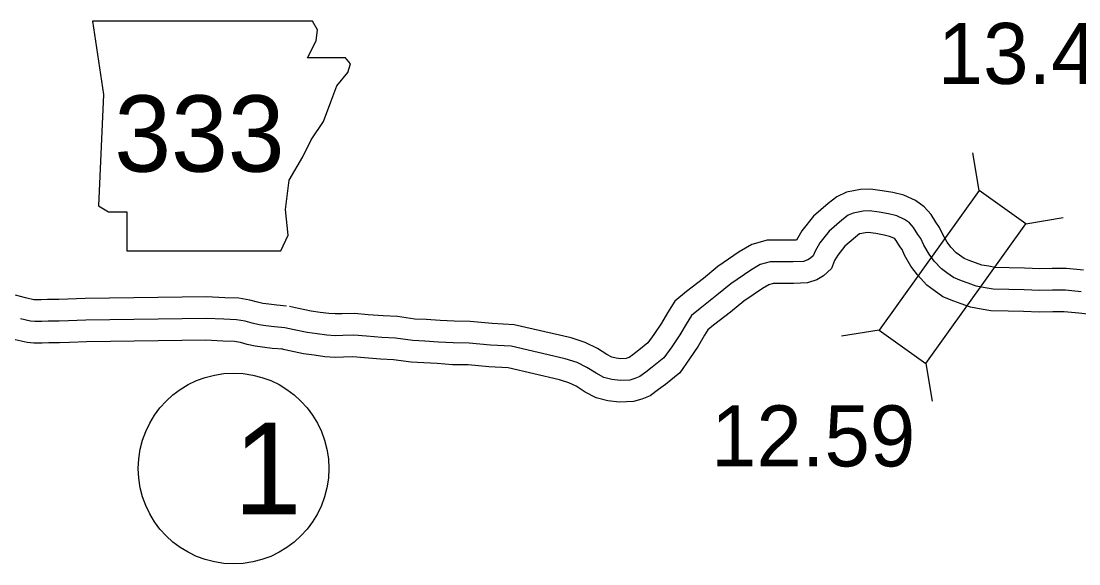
# Model space of a CAD drawing. Extents: x -83719 to 153526, y -11835 to 11446.
# Drawn here: x -2257.4 to -2013.5, y 1927.3 to 2052.4 of the extents above; entities that cross this region are included whole.
import ezdxf

# ---------------------------------------------------------------- set-up
doc = ezdxf.new("R2010")
doc.units = 0
for name, color, linetype in [('Level 11', 7, 'Continuous'), ('Level 20', 7, 'Continuous'), ('Level 21', 7, 'Continuous'), ('Level 25', 7, 'Continuous'), ('Level 27', 7, 'Continuous'), ('Level 58', 7, 'Continuous'), ('Level 59', 7, 'Continuous')]:
    doc.layers.add(name, color=color, linetype=linetype)

msp = doc.modelspace()

# ---------------------------------------------------------------- linework, layer by layer
at = {"layer": 'Level 11'}
for points in [[(-2012.39, 1995), (-2016.34, 1995.43), (-2019.58, 1995.38), (-2022.43, 1995.34), (-2025.96, 1995.49), (-2029.54, 1995.55), (-2032.74, 1995.63), (-2034.24, 1995.9), (-2035.87, 1996.18), (-2037.31, 1996.71), (-2038.78, 1997.21), (-2039.93, 1997.69), (-2040.99, 1998.44), (-2041.79, 1999.03), (-2042.96, 2000.31), (-2043.83, 2001.47), (-2044.75, 2003.09), (-2045.57, 2004.84), (-2046.45, 2006.05), (-2047.54, 2007.82), (-2049.16, 2009.65), (-2051.12, 2011.07), (-2053.83, 2012.3), (-2056.34, 2012.92), (-2058.82, 2013.33), (-2061.52, 2013.68), (-2063.79, 2013.62), (-2067.06, 2012.99), (-2069.3, 2011.95), (-2071.32, 2010.38), (-2074.65, 2007.48), (-2077.36, 2004.12), (-2078.6, 2001.96), (-2079.44, 2001.92), (-2082.09, 2001.95), (-2085.33, 2001.9), (-2088.89, 2000.96), (-2091.78, 1999.25), (-2096.77, 1995.87), (-2100.08, 1993.12), (-2103.97, 1990.1), (-2106.65, 1987.89), (-2108.35, 1985.16), (-2109.72, 1982.8), (-2111.5, 1980.19), (-2112.88, 1978.21), (-2114.93, 1976.55), (-2116.35, 1975.5), (-2117.2, 1974.87), (-2117.5, 1974.75), (-2117.89, 1974.64), (-2119.08, 1974.58), (-2120.21, 1974.72), (-2121.22, 1974.98), (-2122.33, 1975.56), (-2124.51, 1976.95), (-2127.31, 1978.32), (-2130.6, 1979.4), (-2143.69, 1982.41), (-2148.83, 1982.72), (-2153.86, 1983.19), (-2157.59, 1983.21), (-2160.8, 1983.42), (-2164.05, 1983.65), (-2166.65, 1983.74), (-2170.61, 1984.29), (-2173.91, 1984.45), (-2177.39, 1984.74), (-2180.56, 1985.02), (-2183.38, 1984.97), (-2184.99, 1984.91), (-2186.45, 1984.98), (-2188.45, 1985.27), (-2190.58, 1985.58), (-2193.44, 1986.17), (-2195.55, 1986.63)], [(-2008.19, 1984.46), (-2013.49, 1985.06), (-2016.81, 1985.42), (-2019.43, 1985.38), (-2022.58, 1985.34), (-2026.25, 1985.5), (-2029.74, 1985.55), (-2033.74, 1985.65), (-2035.97, 1986.05), (-2038.48, 1986.48), (-2040.64, 1987.28), (-2042.3, 1987.84), (-2044.82, 1988.89), (-2046.84, 1990.33), (-2048.5, 1991.54), (-2050.67, 1993.93), (-2052.21, 1995.97), (-2053.64, 1998.49), (-2054.22, 1999.74), (-2054.76, 2000.47), (-2055.6, 2001.84), (-2055.93, 2002.2), (-2056.17, 2002.38), (-2057.12, 2002.81), (-2058.35, 2003.12), (-2060.28, 2003.43), (-2062.04, 2003.67), (-2062.7, 2003.65), (-2063.96, 2003.4), (-2064.06, 2003.36), (-2064.96, 2002.65), (-2067.42, 2000.52), (-2069.08, 1998.45), (-2069.79, 1997.23), (-2070.48, 1995.43), (-2072.35, 1993.74), (-2073.89, 1992.81), (-2076.08, 1992.07), (-2079.25, 1991.92), (-2082.06, 1991.95), (-2083.95, 1991.92), (-2084.99, 1991.64), (-2086.43, 1990.8), (-2090.75, 1987.86), (-2093.82, 1985.32), (-2097.72, 1982.29), (-2099.02, 1981.22), (-2099.78, 1980), (-2101.26, 1977.46), (-2103.26, 1974.52), (-2105.48, 1971.34), (-2108.81, 1968.64), (-2110.39, 1967.47), (-2112.32, 1966.03), (-2114.29, 1965.27), (-2116.23, 1964.71), (-2119.44, 1964.55), (-2122.1, 1964.87), (-2124.84, 1965.6), (-2127.33, 1966.88), (-2129.42, 1968.22), (-2131.09, 1969.04), (-2133.28, 1969.75), (-2145.12, 1972.48), (-2149.59, 1972.75), (-2154.36, 1973.19), (-2157.96, 1973.21), (-2161.48, 1973.45), (-2164.57, 1973.66), (-2167.5, 1973.76), (-2171.54, 1974.32), (-2174.57, 1974.47), (-2178.23, 1974.77), (-2180.92, 1975.01), (-2183.1, 1974.97), (-2185.03, 1974.9), (-2187.43, 1975.01), (-2189.89, 1975.38), (-2192.3, 1975.72), (-2195.51, 1976.38), (-2197.67, 1976.85)], [(-2196.21, 1986.72), (-2198.49, 1986.91), (-2200.35, 1987.14), (-2201.66, 1987.35), (-2202.96, 1987.61), (-2204.68, 1988.1), (-2207.22, 1988.53), (-2210.46, 1988.66), (-2214.69, 1988.86), (-2242.67, 1988.51), (-2246.68, 1988.29), (-2248.75, 1988.26), (-2251.36, 1988.21), (-2252.83, 1988.14), (-2254.04, 1988.14), (-2254.51, 1988.19), (-2256.45, 1988.62), (-2258.76, 1989.23)], [(-2197.01, 1976.75), (-2199.53, 1976.96), (-2201.74, 1977.24), (-2203.43, 1977.5), (-2205.33, 1977.89), (-2206.87, 1978.33), (-2208.27, 1978.56), (-2210.9, 1978.67), (-2214.86, 1978.86), (-2242.34, 1978.51), (-2246.32, 1978.3), (-2248.58, 1978.26), (-2251.04, 1978.22), (-2252.57, 1978.14), (-2254.49, 1978.14), (-2256.09, 1978.29), (-2258.82, 1978.91)]]:
    msp.add_lwpolyline(points, dxfattribs=at)
at = {"layer": 'Level 20'}
for p, q in [((-2036.46, 2013.4), (-2037.9, 2022.08)), ((-2025.72, 2005.72), (-2017.04, 2007.16)), ((-2059.5, 1981.19), (-2068.18, 1979.75)), ((-2048.76, 1973.51), (-2047.32, 1964.83))]:
    msp.add_line(p, q, dxfattribs=at)
msp.add_lwpolyline([(-2036.46, 2013.4), (-2059.5, 1981.19), (-2048.76, 1973.51), (-2025.72, 2005.72)], close=True, dxfattribs=at)
at = {"layer": 'Level 21'}
msp.add_lwpolyline([(-2240.99, 2052.45), (-2238.45, 2035.53), (-2239.58, 2009.87), (-2237.32, 2008.46), (-2233.09, 2008.46), (-2233.09, 1999.44), (-2197.56, 1999.44), (-2195.87, 2003.1), (-2196.44, 2009.03), (-2195.59, 2015.79), (-2192.49, 2021.15), (-2190.51, 2025.1), (-2187.69, 2029.33), (-2186, 2033.84), (-2184.59, 2037.5), (-2182.06, 2040.61), (-2181.49, 2042.58), (-2182.62, 2043.99), (-2191.36, 2043.99), (-2189.39, 2047.94), (-2189.1, 2050.47), (-2190.27, 2052.42)], close=True, dxfattribs=at)
at = {"layer": 'Level 27'}
msp.add_circle((-2208.45, 1949.27), 22, dxfattribs=at)
at = {"layer": 'Level 59'}
for points in [[(-2012.94, 1990.03), (-2016.57, 1990.42), (-2019.51, 1990.38), (-2022.51, 1990.34), (-2026.1, 1990.5), (-2029.64, 1990.55), (-2033.24, 1990.64), (-2035.1, 1990.97), (-2037.17, 1991.33), (-2038.97, 1992), (-2040.54, 1992.53), (-2042.38, 1993.29), (-2043.91, 1994.39), (-2045.15, 1995.29), (-2046.82, 1997.12), (-2048.02, 1998.72), (-2049.19, 2000.79), (-2049.9, 2002.29), (-2050.6, 2003.26), (-2051.57, 2004.83), (-2052.54, 2005.93), (-2053.64, 2006.73), (-2055.48, 2007.56), (-2057.35, 2008.02), (-2059.55, 2008.38), (-2061.78, 2008.67), (-2063.25, 2008.64), (-2065.51, 2008.19), (-2066.68, 2007.66), (-2068.14, 2006.52), (-2071.03, 2004), (-2073.22, 2001.29), (-2074.32, 1999.38), (-2074.72, 1998.34), (-2075.35, 1997.77), (-2076.01, 1997.37), (-2077.01, 1997.03), (-2079.34, 1996.92), (-2082.08, 1996.95), (-2084.64, 1996.91), (-2086.94, 1996.3), (-2089.1, 1995.02), (-2093.76, 1991.87), (-2096.95, 1989.22), (-2100.84, 1986.2), (-2102.84, 1984.55), (-2104.07, 1982.58), (-2105.49, 1980.13), (-2107.38, 1977.35), (-2109.18, 1974.78), (-2111.87, 1972.6), (-2113.37, 1971.49), (-2114.76, 1970.45), (-2115.89, 1970.01), (-2117.06, 1969.67), (-2119.26, 1969.57), (-2121.16, 1969.79), (-2123.03, 1970.29), (-2124.83, 1971.22), (-2126.97, 1972.58), (-2129.2, 1973.68), (-2131.94, 1974.58), (-2144.41, 1977.45), (-2149.21, 1977.73), (-2154.11, 1978.19), (-2157.77, 1978.21), (-2161.14, 1978.43), (-2164.31, 1978.66), (-2167.07, 1978.75), (-2171.07, 1979.31), (-2174.24, 1979.46), (-2177.81, 1979.75), (-2180.74, 1980.01), (-2183.24, 1979.97), (-2185.01, 1979.9), (-2186.94, 1980), (-2189.17, 1980.32), (-2191.44, 1980.65), (-2194.48, 1981.28), (-2196.61, 1981.74)], [(-2196.61, 1981.74), (-2199.01, 1981.93), (-2201.04, 1982.19), (-2202.54, 1982.42), (-2204.14, 1982.75), (-2205.78, 1983.22), (-2207.75, 1983.54), (-2210.68, 1983.67), (-2214.78, 1983.86), (-2242.5, 1983.51), (-2246.5, 1983.3), (-2248.67, 1983.26), (-2251.2, 1983.22), (-2252.7, 1983.14), (-2254.27, 1983.14), (-2255.3, 1983.24), (-2257.63, 1983.77)]]:
    msp.add_lwpolyline(points, dxfattribs=at)

# ---------------------------------------------------------------- texts
at = {"layer": 'Level 21'}
msp.add_text('333', height=17.6, dxfattribs=at).set_placement((-2235.96, 2017.73))
at = {"layer": 'Level 25'}
msp.add_text('13.40', height=14.08, dxfattribs=at).set_placement((-2046.01, 2037.96))
at = {"layer": 'Level 27'}
msp.add_text('1', height=21.12, dxfattribs=at).set_placement((-2208.45, 1938.71))
at = {"layer": 'Level 58'}
msp.add_text('12.59', height=14.08, dxfattribs=at).set_placement((-2098.31, 1949.74))

doc.saveas('drawing.dxf')
